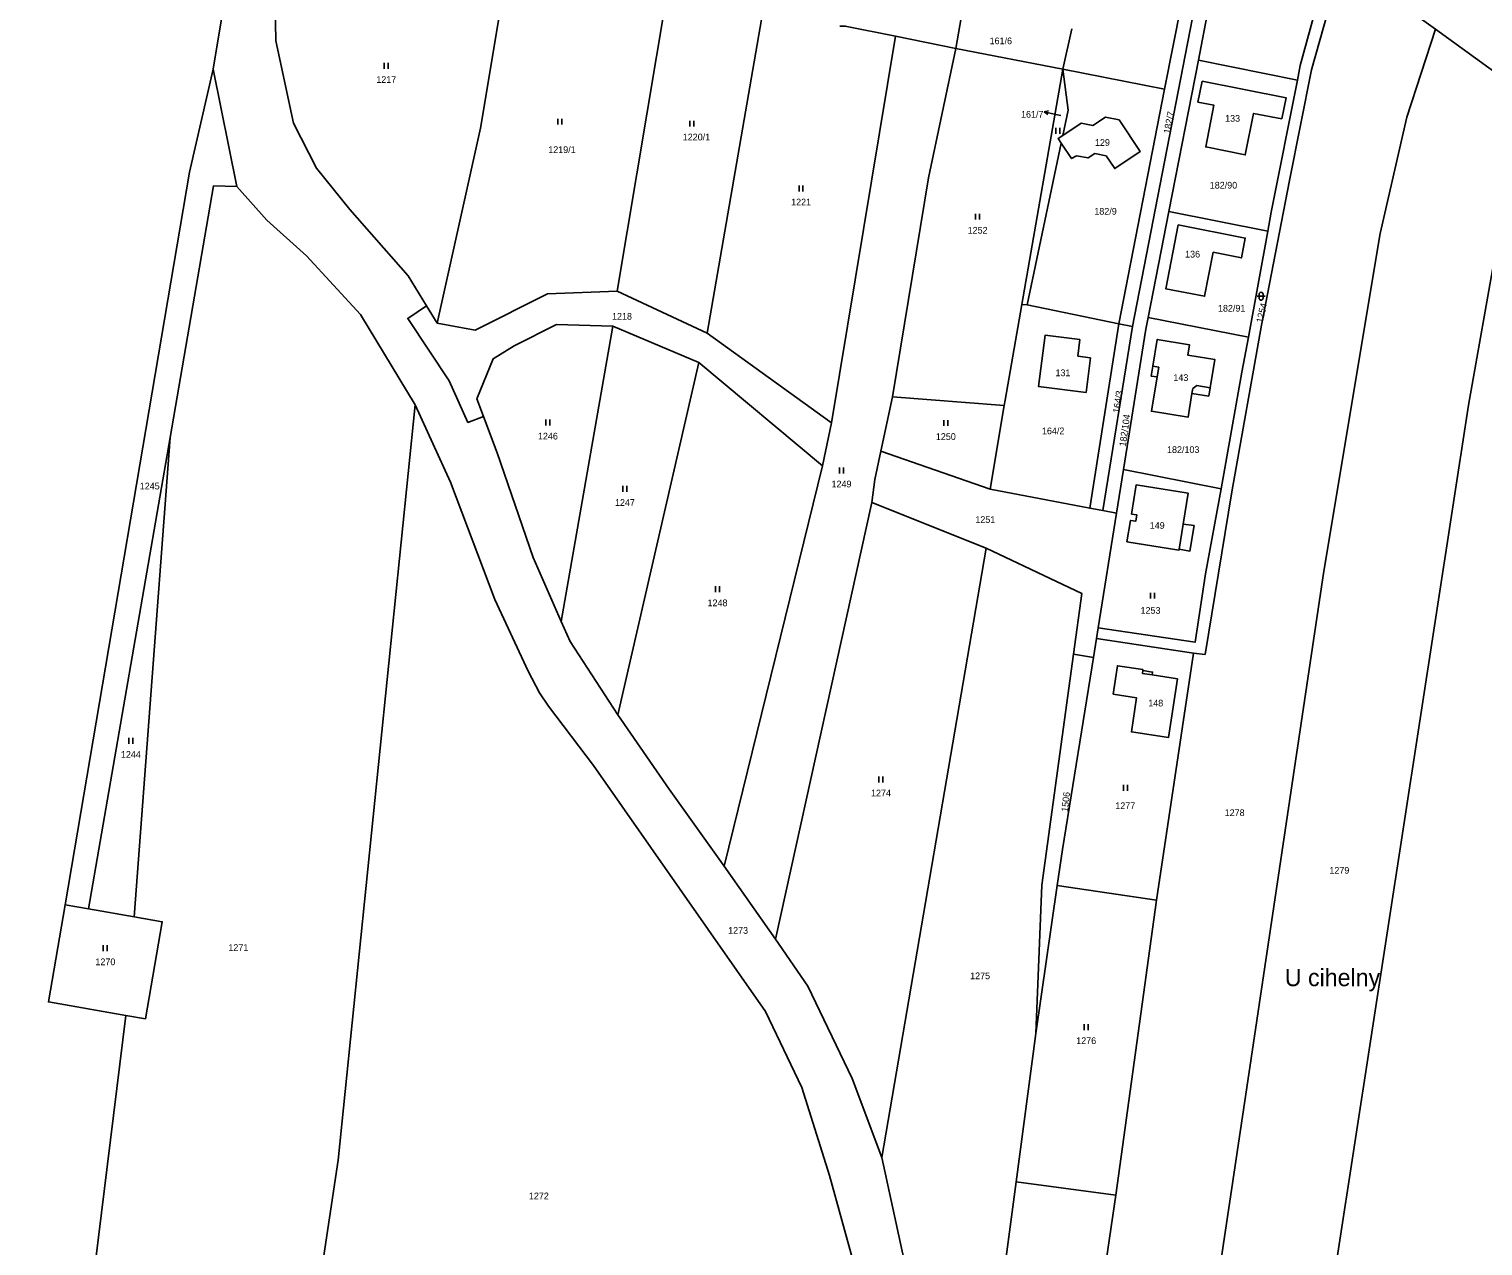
# Model space of a CAD drawing. Extents: x -746176 to -739709, y -1128407 to -1124482.
# Drawn here: x -742234.3 to -741865.4, y -1126742.1 to -1126433.2 of the extents above; entities that cross this region are included whole.
import ezdxf

# ---------------------------------------------------------------- set-up
doc = ezdxf.new("R2010")
doc.units = 0
for name, color, linetype in [('Hranice parcel', 7, 'Continuous'), ('Parcelní čísla', 7, 'Continuous'), ('Pop  PČ popisy', 7, 'Continuous'), ('Vnitřní kresba', 7, 'Continuous'), ('Značky kultur', 7, 'Continuous')]:
    doc.layers.add(name, color=color, linetype=linetype)

msp = doc.modelspace()

# ---------------------------------------------------------------- linework, layer by layer
at = {"layer": 'Hranice parcel'}
for p, q in [((-741999.11, -1126438.17), (-741996.32, -1126421.94)), ((-742072.53, -1126424.54), (-742085.13, -1126499.75)), ((-742048.06, -1126428.34), (-742062.27, -1126510.43)), ((-741971.96, -1126443.41), (-741969.67, -1126433.17)), ((-741854.95, -1126449.53), (-741877.38, -1126433.3)), ((-742030.73, -1126533.18), (-742014.43, -1126435)), ((-742014.43, -1126435), (-741999.11, -1126438.17)), ((-741999.11, -1126438.17), (-741971.96, -1126443.41)), ((-742181.63, -1126473.18), (-742187.6, -1126443.43)), ((-741971.96, -1126443.41), (-741982.39, -1126503.11)), ((-741971.96, -1126443.41), (-741946.15, -1126448.52)), ((-741937.58, -1126441.15), (-741945.07, -1126479.55)), ((-741937.58, -1126441.15), (-741912.45, -1126446.2)), ((-741946.15, -1126448.52), (-741957.75, -1126508.02)), ((-741981.04, -1126503.23), (-741972.39, -1126462.23)), ((-741945.07, -1126479.55), (-741950.3, -1126506.42)), ((-741945.07, -1126479.55), (-741919.95, -1126484.52)), ((-741924.9, -1126511.47), (-741919.95, -1126484.52)), ((-742062.27, -1126510.43), (-742085.13, -1126499.75)), ((-742130.78, -1126507.86), (-742133.47, -1126503.52)), ((-741982.39, -1126503.11), (-741981.04, -1126503.23)), ((-741981.04, -1126503.23), (-741957.75, -1126508.02)), ((-741950.3, -1126506.42), (-741924.9, -1126511.47)), ((-742099.34, -1126583.64), (-742086.2, -1126508.61)), ((-742086.2, -1126508.61), (-742064.37, -1126517.89)), ((-742030.73, -1126533.18), (-742062.27, -1126510.43)), ((-741965.17, -1126554.82), (-741957.75, -1126508.02)), ((-741961.8, -1126555.46), (-741954.32, -1126508.73)), ((-741957.75, -1126508.02), (-741954.32, -1126508.73)), ((-742084.93, -1126607.27), (-742064.37, -1126517.89)), ((-742064.37, -1126517.89), (-742032.96, -1126544.11)), ((-742015.23, -1126526.56), (-742018.18, -1126540.36)), ((-741986.84, -1126528.78), (-742015.23, -1126526.56)), ((-741986.84, -1126528.78), (-741990.4, -1126550.02)), ((-742032.96, -1126544.11), (-742030.73, -1126533.18)), ((-742219.28, -1126656.58), (-742198.58, -1126536.93)), ((-742198.58, -1126536.93), (-742207.72, -1126658.58)), ((-742018.18, -1126540.36), (-741990.4, -1126550.02)), ((-742057.95, -1126645.76), (-742032.96, -1126544.11)), ((-741958.35, -1126556.11), (-741956.57, -1126544.99)), ((-741956.57, -1126544.99), (-741931.8, -1126549.92)), ((-741990.4, -1126550.02), (-741965.17, -1126554.82)), ((-742020.49, -1126553.4), (-742044.92, -1126664.26)), ((-741991.43, -1126565.04), (-742020.49, -1126553.4)), ((-741965.17, -1126554.82), (-741961.8, -1126555.46)), ((-741961.8, -1126555.46), (-741958.35, -1126556.11)), ((-741958.35, -1126556.11), (-741963.01, -1126585.21)), ((-742017.91, -1126719.67), (-741991.43, -1126565.04)), ((-741963.45, -1126587.97), (-741964.22, -1126592.75)), ((-741963.01, -1126585.21), (-741963.45, -1126587.97)), ((-741963.45, -1126587.97), (-741938.82, -1126591.67)), ((-741964.22, -1126592.75), (-741969.26, -1126591.89)), ((-741938.82, -1126591.67), (-741948.24, -1126654.37)), ((-742044.92, -1126664.26), (-742057.95, -1126645.76)), ((-741973.39, -1126650.59), (-741978.81, -1126688.21)), ((-741948.24, -1126654.37), (-741973.39, -1126650.59)), ((-741958.56, -1126729.22), (-741948.24, -1126654.37)), ((-742225.19, -1126655.56), (-742219.28, -1126656.58)), ((-742207.72, -1126658.58), (-742219.28, -1126656.58)), ((-741978.81, -1126688.21), (-741983.83, -1126725.85)), ((-741983.83, -1126725.85), (-741958.56, -1126729.22))]:
    msp.add_line(p, q, dxfattribs=at)
for points in [[(-742187.6, -1126443.43), (-742182.48, -1126412.17), (-742177.55, -1126374.98), (-742174.74, -1126350.1), (-742174.68, -1126346.91)], [(-742133.47, -1126503.52), (-742138.17, -1126495.9), (-742152.98, -1126479.01), (-742161.38, -1126468.51), (-742167.25, -1126457.12), (-742171.72, -1126436.22), (-742172.13, -1126413.04), (-742170.12, -1126398.06)], [(-741954.32, -1126508.73), (-741938.56, -1126427.78), (-741932.77, -1126409.29)], [(-741936.11, -1126408.24), (-741941.9, -1126426.74), (-741946.15, -1126448.52)], [(-741925.07, -1126408.25), (-741929.41, -1126410.36), (-741935.06, -1126428.26), (-741937.58, -1126441.15)], [(-742130.78, -1126507.86), (-742119.81, -1126458.38), (-742113.18, -1126418.78)], [(-741912.45, -1126446.2), (-741911.72, -1126442.48), (-741904.57, -1126416.23)], [(-741898.42, -1126419.6), (-741902.57, -1126421.34), (-741908.84, -1126443.59), (-741914.46, -1126471.66), (-741921.58, -1126508.41), (-741929.05, -1126550.68), (-741935.86, -1126591.95), (-741938.82, -1126591.67)], [(-741877.38, -1126433.3), (-741887.7, -1126425.84), (-741898.42, -1126419.6)], [(-742028.56, -1126432.53), (-742027.22, -1126432.46), (-742014.43, -1126435)], [(-741949.18, -1126838.52), (-741941.96, -1126813.45), (-741924.2, -1126694.57), (-741905.72, -1126570.83), (-741891.45, -1126485.12), (-741884.64, -1126455.59), (-741877.38, -1126433.3)], [(-741999.11, -1126438.17), (-742006.04, -1126471.03), (-742015.23, -1126526.56)], [(-742187.6, -1126443.43), (-742193.63, -1126469.56), (-742225.19, -1126655.56)], [(-741971.96, -1126460.21), (-741970.61, -1126453.82), (-741971.96, -1126443.41)], [(-741916.39, -1126456.06), (-741923.58, -1126454.64), (-741925.69, -1126465.18), (-741935.73, -1126463.15), (-741933.62, -1126452.56), (-741937.69, -1126451.75), (-741936.62, -1126446.48), (-741915.3, -1126450.71), (-741916.39, -1126456.06)], [(-741919.95, -1126484.52), (-741919.07, -1126479.73), (-741912.45, -1126446.2)], [(-741854.95, -1126449.53), (-741869, -1126528.7), (-741885.6, -1126636.32), (-741902.19, -1126743.95), (-741911.69, -1126803.9), (-741921.19, -1126863.86)], [(-741971.96, -1126460.21), (-741967.36, -1126457.11), (-741964.34, -1126457.73), (-741961.18, -1126455.63), (-741957.72, -1126456.31), (-741952.34, -1126464.28), (-741958.81, -1126468.63), (-741961.01, -1126465.4), (-741963.86, -1126464.82), (-741965.59, -1126465.96), (-741968.54, -1126465.39), (-741969.75, -1126466.13), (-741972.39, -1126462.23)], [(-741972.39, -1126462.23), (-741973.19, -1126461.04), (-741971.96, -1126460.21)], [(-742198.58, -1126536.93), (-742187.57, -1126473.06), (-742181.63, -1126473.18)], [(-742136.32, -1126528.63), (-742150.26, -1126505.72), (-742163.9, -1126490.76), (-742174, -1126481.74), (-742181.63, -1126473.18)], [(-741933.81, -1126489.89), (-741936.01, -1126501.05), (-741945.87, -1126499.14), (-741942.7, -1126482.95), (-741925.67, -1126486.3), (-741926.64, -1126491.33), (-741933.81, -1126489.89)], [(-742085.13, -1126499.75), (-742102.79, -1126500.44), (-742121.1, -1126509.69), (-742130.78, -1126507.86)], [(-742133.47, -1126503.52), (-742138.24, -1126506.67), (-742127.69, -1126522.49), (-742122.99, -1126533.1), (-742119.02, -1126531.6)], [(-741982.39, -1126503.11), (-741986.61, -1126527.43), (-741986.84, -1126528.78)], [(-741950.3, -1126506.42), (-741950.88, -1126509.4), (-741956.57, -1126544.99)], [(-742119.02, -1126531.6), (-742120.68, -1126527.1), (-742116.58, -1126516.91), (-742111.25, -1126513.62), (-742100.5, -1126508.24), (-742086.2, -1126508.61)], [(-741966.09, -1126525.52), (-741978.13, -1126523.98), (-741976.5, -1126510.95), (-741967.68, -1126512.06), (-741968.17, -1126516.26), (-741964.97, -1126516.71), (-741966.09, -1126525.52)], [(-741949.54, -1126521.3), (-741949.14, -1126518.84), (-741948.01, -1126512), (-741939.86, -1126513.36), (-741940.29, -1126515.97), (-741933.44, -1126517.1), (-741934.6, -1126524.26), (-741934.95, -1126526.39), (-741939.23, -1126525.71), (-741940.21, -1126531.75), (-741949.49, -1126530.23), (-741948.05, -1126521.55), (-741949.54, -1126521.3)], [(-741931.8, -1126549.92), (-741926.53, -1126520.32), (-741924.9, -1126511.47)], [(-742178.83, -1126851.05), (-742171.32, -1126822.78), (-742155.89, -1126720.33), (-742136.32, -1126528.63)], [(-741999.58, -1126809.75), (-742010.53, -1126795.36), (-742015.95, -1126779.71), (-742017.83, -1126773.98), (-742019.18, -1126767.51), (-742024.98, -1126746.93), (-742031.2, -1126724.22), (-742038.23, -1126701.93), (-742047.45, -1126682.61), (-742091.11, -1126620.17), (-742102.48, -1126605.07), (-742104.79, -1126601.7), (-742107.64, -1126596.22), (-742116.14, -1126577.99), (-742127.39, -1126548.21), (-742136.32, -1126528.63)], [(-742099.34, -1126583.64), (-742106.44, -1126567.33), (-742115.57, -1126540.78), (-742119.02, -1126531.6)], [(-742018.18, -1126540.36), (-742019.72, -1126547.57), (-742020.49, -1126553.4)], [(-741963.01, -1126585.21), (-741938.41, -1126588.9), (-741935.8, -1126571.55), (-741931.8, -1126549.92)], [(-741942.48, -1126565.27), (-741942.51, -1126565.48), (-741955.71, -1126563.36), (-741954.79, -1126557.96), (-741953.49, -1126558.18), (-741953.24, -1126556.54), (-741954.54, -1126556.33), (-741953.34, -1126548.91), (-741940.2, -1126551.04), (-741941.46, -1126558.9), (-741938.67, -1126559.28), (-741939.72, -1126565.72), (-741942.48, -1126565.27)], [(-741969.26, -1126591.89), (-741967.19, -1126576.48), (-741991.43, -1126565.04)], [(-742084.93, -1126607.27), (-742096.98, -1126588.69), (-742099.34, -1126583.64)], [(-741978.81, -1126688.21), (-741977.33, -1126650.54), (-741969.26, -1126591.89)], [(-741964.22, -1126592.75), (-741972.08, -1126641.48), (-741973.39, -1126650.59)], [(-741959.21, -1126602.06), (-741958.13, -1126594.85), (-741951.65, -1126595.81), (-741951.69, -1126596.09), (-741949.2, -1126596.45), (-741949.3, -1126597.17), (-741942.9, -1126598.15), (-741945.13, -1126613.03), (-741954.59, -1126611.62), (-741953.3, -1126602.96), (-741959.21, -1126602.06)], [(-742057.95, -1126645.76), (-742071.88, -1126626.21), (-742084.93, -1126607.27)], [(-742225.19, -1126655.56), (-742229.45, -1126680.19), (-742209.78, -1126683.59)], [(-742209.78, -1126683.59), (-742204.82, -1126684.45), (-742200.55, -1126659.82), (-742207.72, -1126658.58)], [(-742044.92, -1126664.26), (-742036.67, -1126676.18), (-742025.42, -1126699.58), (-742017.91, -1126719.67)], [(-742209.78, -1126683.59), (-742220.66, -1126771.42), (-742228.09, -1126808.59), (-742234.35, -1126828.88)], [(-742017.91, -1126719.67), (-742012.75, -1126743.47), (-742007.6, -1126764.33), (-742004.26, -1126772.24), (-741997.55, -1126789.67), (-741994.96, -1126793.61)], [(-741994.96, -1126793.61), (-741988.23, -1126758.85), (-741983.83, -1126725.85)], [(-741958.56, -1126729.22), (-741962.62, -1126756.79), (-741970.12, -1126797.93), (-741975.77, -1126814.25)]]:
    msp.add_lwpolyline(points, dxfattribs=at)
at = {"layer": 'Pop  PČ popisy'}
for p, q in [((-741976.69, -1126454.23), (-741975.61, -1126453.96)), ((-741973.77, -1126454.9), (-741976.69, -1126454.23)), ((-741976.69, -1126454.23), (-741975.83, -1126454.94)), ((-741972.47, -1126455.21), (-741973.77, -1126454.9))]:
    msp.add_line(p, q, dxfattribs=at)
at = {"layer": 'Vnitřní kresba'}
for p, q in [((-741949.14, -1126518.84), (-741947.64, -1126519.08)), ((-741947.64, -1126519.08), (-741948.05, -1126521.55)), ((-741939.03, -1126524.51), (-741939.23, -1126525.71)), ((-741937.97, -1126523.73), (-741939.03, -1126524.51)), ((-741934.6, -1126524.26), (-741937.97, -1126523.73)), ((-741942.48, -1126565.27), (-741941.46, -1126558.9)), ((-741951.69, -1126596.09), (-741951.8, -1126596.82)), ((-741951.8, -1126596.82), (-741949.3, -1126597.17))]:
    msp.add_line(p, q, dxfattribs=at)
at = {"layer": 'Značky kultur'}
for p, q in [((-742144.22, -1126443.34), (-742144.22, -1126441.84)), ((-742143.22, -1126443.34), (-742143.22, -1126441.84)), ((-742100.15, -1126457.48), (-742100.15, -1126455.98)), ((-742099.15, -1126457.48), (-742099.15, -1126455.98)), ((-742066.66, -1126458), (-742066.66, -1126456.5)), ((-742065.66, -1126458), (-742065.66, -1126456.5)), ((-741973.78, -1126459.82), (-741973.78, -1126458.32)), ((-741972.78, -1126459.82), (-741972.78, -1126458.32)), ((-742038.94, -1126474.45), (-742038.94, -1126472.95)), ((-742037.94, -1126474.45), (-742037.94, -1126472.95)), ((-741994.14, -1126481.6), (-741994.14, -1126480.1)), ((-741993.14, -1126481.6), (-741993.14, -1126480.1)), ((-741922.67, -1126501.05), (-741920.67, -1126501.05)), ((-741922.17, -1126500.55), (-741922.17, -1126501.55)), ((-741921.17, -1126501.55), (-741921.17, -1126500.55)), ((-742103.2, -1126533.86), (-742103.2, -1126532.36)), ((-742102.2, -1126533.86), (-742102.2, -1126532.36)), ((-742002.21, -1126533.97), (-742002.21, -1126532.47)), ((-742001.21, -1126533.97), (-742001.21, -1126532.47)), ((-742028.69, -1126546.02), (-742028.69, -1126544.52)), ((-742027.69, -1126546.02), (-742027.69, -1126544.52)), ((-742083.65, -1126550.71), (-742083.65, -1126549.21)), ((-742082.65, -1126550.71), (-742082.65, -1126549.21)), ((-742060.15, -1126576.18), (-742060.15, -1126574.68)), ((-742059.15, -1126576.18), (-742059.15, -1126574.68)), ((-741949.74, -1126577.8), (-741949.74, -1126576.3)), ((-741948.74, -1126577.8), (-741948.74, -1126576.3)), ((-742209.04, -1126614.66), (-742209.04, -1126613.16)), ((-742208.04, -1126614.66), (-742208.04, -1126613.16)), ((-742018.66, -1126624.45), (-742018.66, -1126622.95)), ((-742017.66, -1126624.45), (-742017.66, -1126622.95)), ((-741956.57, -1126626.59), (-741956.57, -1126625.09)), ((-741955.57, -1126626.59), (-741955.57, -1126625.09)), ((-742215.51, -1126667.3), (-742215.51, -1126665.8)), ((-742214.51, -1126667.3), (-742214.51, -1126665.8)), ((-741966.58, -1126687.31), (-741966.58, -1126685.81)), ((-741965.58, -1126687.31), (-741965.58, -1126685.81))]:
    msp.add_line(p, q, dxfattribs=at)
for centre, start, end in [((-741921.67, -1126500.55), 0, 180), ((-741921.67, -1126501.55), 180, 359.9879)]:
    msp.add_arc(centre, 0.5, start, end, dxfattribs=at)

# ---------------------------------------------------------------- texts
at = {"layer": 'Parcelní čísla'}
for s, p in [('161/6', (-741990.57, -1126437.08)), ('1217', (-742146.22, -1126446.89)), ('161/7', (-741982.6, -1126455.73)), ('133', (-741930.79, -1126456.75)), ('1219/1', (-742102.58, -1126464.69)), ('1220/1', (-742068.45, -1126461.49)), ('129', (-741963.83, -1126462.88)), ('182/90', (-741934.69, -1126473.72)), ('1221', (-742040.94, -1126478)), ('182/9', (-741963.99, -1126480.34)), ('1252', (-741996.14, -1126485.15)), ('136', (-741940.95, -1126491.22)), ('182/91', (-741932.61, -1126504.95)), ('1218', (-742086.4, -1126507)), ('131', (-741973.85, -1126521.34)), ('143', (-741943.93, -1126522.55)), ('1246', (-742105.2, -1126537.41)), ('1250', (-742004.21, -1126537.52)), ('164/2', (-741977.28, -1126536.08)), ('182/103', (-741945.54, -1126540.83)), ('1249', (-742030.69, -1126549.57)), ('1245', (-742206.26, -1126550.09)), ('1247', (-742085.65, -1126554.26)), ('1251', (-741994.19, -1126558.59)), ('149', (-741949.93, -1126560.09)), ('1248', (-742062.15, -1126579.73)), ('1253', (-741952.26, -1126581.65)), ('148', (-741950.3, -1126605.17)), ('1244', (-742211.04, -1126618.21)), ('1274', (-742020.66, -1126628)), ('1277', (-741958.68, -1126631.24)), ('1278', (-741930.91, -1126633)), ('1279', (-741904.33, -1126647.63)), ('1273', (-742056.93, -1126662.88)), ('1271', (-742183.77, -1126667.23)), ('1270', (-742217.51, -1126670.85)), ('1275', (-741995.51, -1126674.41)), ('1276', (-741968.58, -1126690.86)), ('1272', (-742107.49, -1126730.27))]:
    msp.add_text(s, height=1.7, dxfattribs=at).set_placement(p)
for s, rotation, p in [('182/7', 79, (-741944.77, -1126459.91)), ('1254', 77, (-741921.27, -1126507.92)), ('164/3', 81, (-741957.64, -1126530.79)), ('182/104', 82, (-741956.01, -1126539.29)), ('1506', 84, (-741970.68, -1126632))]:
    msp.add_text(s, height=1.7, rotation=rotation, dxfattribs=at).set_placement(p)
at = {"layer": 'Pop  PČ popisy'}
msp.add_text('U cihelny', height=4.4, dxfattribs=at).set_placement((-741915.64, -1126676.18))

doc.saveas('drawing.dxf')
